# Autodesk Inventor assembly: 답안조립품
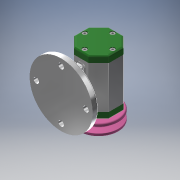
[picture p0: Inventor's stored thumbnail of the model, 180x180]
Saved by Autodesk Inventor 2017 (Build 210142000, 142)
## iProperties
Part Number: 답안조립품
Material: 일반
Document SubType Name: Assembly
Designer: 00-00
Author: 00-00
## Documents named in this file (14)
- C:\Users\00-00\Desktop\710204V1025\답안조립품.iam
- C:\Users\00-00\Desktop\710204V1025\본체.ipt
- C:\Users\00-00\Desktop\710204V1025\베어링 15 x 32 x 9.ipt
- C:\Users\00-00\Desktop\710204V1025\앞커버.ipt
- C:\Users\00-00\Desktop\710204V1025\뒤커버.ipt
- C:\Users\00-00\Desktop\710204V1025\볼트 M4 x 12.ipt
- C:\Users\00-00\Desktop\710204V1025\오일 실 15 25 7.ipt
- C:\Users\00-00\Desktop\710204V1025\축.ipt
- C:\Users\00-00\Desktop\710204V1025\키 3 x 3 x 12.ipt
- C:\Users\00-00\Desktop\710204V1025\V벨트풀리.ipt
- C:\Users\00-00\Desktop\710204V1025\와셔 8x17.ipt
- C:\Users\00-00\Desktop\710204V1025\스프링와셔 8.ipt
- C:\Users\00-00\Desktop\710204V1025\너트 M8.ipt
- C:\Users\00-00\Desktop\710204V1025\고무캡.ipt
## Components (2 placed, 2 different names)
1. V벨트풀리:1
2. 고무캡:1
